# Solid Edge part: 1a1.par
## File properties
Author: edge
Template: jis part.par
Last saved by: edge
Revision: 18
Application: Solid Edge
文書内容のタイプ: 0
Accuracy: 0.990
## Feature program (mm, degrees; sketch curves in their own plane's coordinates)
sketch for "ExtrudedProtrusion_1" plane through (0, 0, 0) normal (1, 0, 0) x-axis (0, 1, 0)
  circle centre (0, 0) radius 20
extrude "ExtrudedProtrusion_1" add finite 150 along +normal  FiniteDepth2 = 150 mm
sketch for "ExtrudedProtrusion_2" plane through (25, 0, 0) normal (1, 0, 0) x-axis (0, 1, 0)
  circle centre (0, 0) radius 22.5
extrude "ExtrudedProtrusion_2" add finite 10 along +normal  Profile_Plane1_Distance = 25 mm
sketch for "ExtrudedCutout_1" plane through (-25, 0, 0) normal (1, 0, 0) x-axis (0, 1, 0)
  circle centre (0, 0) radius 19
extrude "ExtrudedCutout_1" cut finite 2 along -normal  Profile_Plane1_Distance = 25 mm
chamfer "Chamfer_2" setback 3
chamfer "Chamfer_3" setback 3
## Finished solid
Body 1: solid body, 13 faces, 12 edges, 0 vertices.
  Faces by surface: plane 6, cylinder 5, cone 2
  Edges by curve: circle 12
Bounding box of the edges (mm): 300.000 x 45.000 x 45.000, from (-150, -22.5, -22.5) to (150, 22.5, 22.5).
Cylindrical faces by radius (mm): R19 x1, R20 x3, R22.5 x1
Conical faces (half-angle, radius in mm at the cone's reference point): 45 deg R17 x1, 45 deg R20 x1
Planar faces by outward normal: +x 3, -x 3
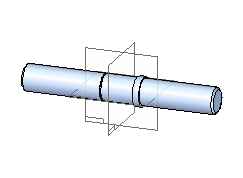
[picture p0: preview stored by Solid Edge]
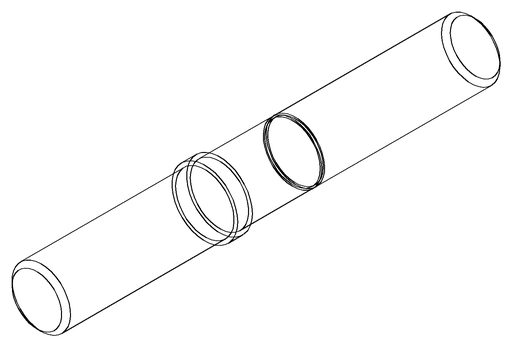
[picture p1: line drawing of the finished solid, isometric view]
